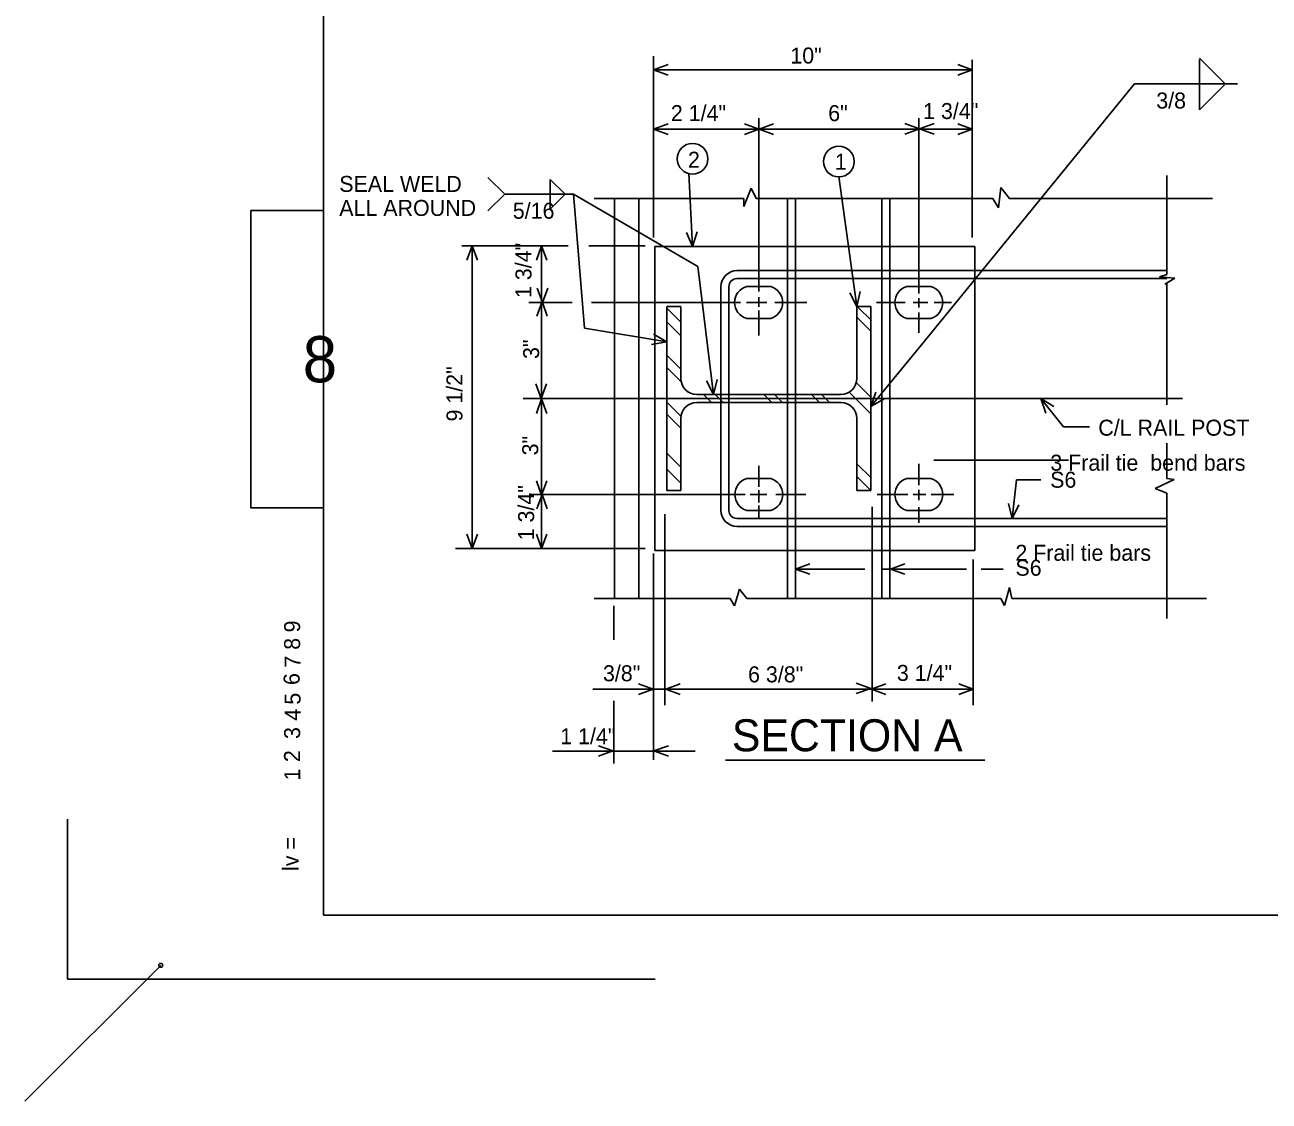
# Model space of a CAD drawing. Extents: x 1509.2 to 1521.3, y 1506 to 1514.6.
# Drawn here: x 1509.476 to 1512.715, y 1506.447 to 1509.25 of the extents above; entities that cross this region are included whole.
import ezdxf

# ---------------------------------------------------------------- set-up
doc = ezdxf.new("R2010")
doc.units = 0
for name, color, linetype in [('Level 1', 7, 'Continuous'), ('Level 2', 7, 'Continuous'), ('Level 3', 7, 'Continuous'), ('Level 4', 7, 'Continuous'), ('Level 49', 7, 'Continuous'), ('Level 5', 7, 'Continuous'), ('Level 50', 7, 'Continuous'), ('Level 6', 7, 'Continuous'), ('Level 7', 7, 'Continuous'), ('Level 8', 7, 'Continuous'), ('Level 9', 7, 'Continuous')]:
    doc.layers.add(name, color=color, linetype=linetype)

msp = doc.modelspace()

# ---------------------------------------------------------------- linework, layer by layer
at = {"layer": 'Level 1'}
for p, q in [((1510.2539, 1506.9309), (1510.2539, 1513.9308)), ((1510.2538, 1507.3188), (1510.2538, 1507.3116)), ((1509.5873, 1507.1817), (1509.5873, 1506.7643)), ((1510.2539, 1506.9309), (1520.7124, 1506.9309)), ((1509.5873, 1506.7643), (1511.1166, 1506.7643))]:
    msp.add_line(p, q, dxfattribs=at)
msp.add_lwpolyline([(1510.2539, 1508.7659), (1510.0647, 1508.7659), (1510.0647, 1507.992), (1510.2539, 1507.992)], close=True, dxfattribs=at)
at = {"layer": 'Level 2'}
for p, q in [((1511.113, 1508.696), (1511.113, 1509.1683)), ((1511.113, 1509.1323), (1511.1506, 1509.1459)), ((1511.113, 1509.1323), (1511.1506, 1509.1459)), ((1511.9419, 1509.1323), (1511.9043, 1509.1459)), ((1511.942, 1508.696), (1511.942, 1509.1588)), ((1512.5335, 1509.1626), (1512.5987, 1509.0973)), ((1512.5335, 1509.159), (1512.5335, 1509.0286)), ((1511.113, 1509.1323), (1511.9419, 1509.1323)), ((1511.113, 1509.1323), (1511.1506, 1509.1186)), ((1511.113, 1509.1323), (1511.1506, 1509.1186)), ((1511.9419, 1509.1323), (1511.9043, 1509.1186)), ((1511.8019, 1508.4068), (1512.3644, 1509.0956)), ((1512.3644, 1509.0956), (1512.6323, 1509.0956)), ((1512.5335, 1509.0286), (1512.5987, 1509.0938)), ((1511.3865, 1508.5549), (1511.3865, 1509.0069)), ((1511.8033, 1508.5501), (1511.8033, 1509.0069)), ((1511.113, 1508.978), (1511.1506, 1508.9917)), ((1511.113, 1508.978), (1511.1506, 1508.9917)), ((1511.113, 1508.978), (1511.9421, 1508.978)), ((1511.113, 1508.978), (1511.1506, 1508.9643)), ((1511.113, 1508.978), (1511.1506, 1508.9643)), ((1511.3867, 1508.9779), (1511.3491, 1508.9916)), ((1511.3867, 1508.9779), (1511.3491, 1508.9643)), ((1511.3873, 1508.978), (1511.4248, 1508.9917)), ((1511.3873, 1508.978), (1511.4248, 1508.9643)), ((1511.8046, 1508.979), (1511.767, 1508.9927)), ((1511.8046, 1508.979), (1511.767, 1508.9653)), ((1511.8052, 1508.979), (1511.8428, 1508.9927)), ((1511.8052, 1508.979), (1511.8428, 1508.9653)), ((1511.9421, 1508.978), (1511.9045, 1508.9917)), ((1511.9421, 1508.978), (1511.9045, 1508.9643)), ((1510.6818, 1508.8523), (1510.7255, 1508.8086)), ((1510.8824, 1508.8086), (1510.8437, 1508.8473)), ((1510.8437, 1508.7699), (1510.8437, 1508.8473)), ((1511.2142, 1508.6725), (1511.2046, 1508.8623)), ((1511.6418, 1508.5164), (1511.595, 1508.8551)), ((1512.449, 1508.5999), (1512.449, 1508.8569)), ((1511.3473, 1508.7764), (1511.3667, 1508.8246)), ((1511.3667, 1508.8246), (1511.3795, 1508.7975)), ((1512.0103, 1508.7733), (1512.0167, 1508.8262)), ((1512.0167, 1508.8262), (1512.0392, 1508.7975)), ((1510.6818, 1508.7649), (1510.7255, 1508.8086)), ((1510.9044, 1508.8086), (1510.7255, 1508.8086)), ((1510.8824, 1508.8086), (1510.8437, 1508.7699)), ((1511.2284, 1508.6201), (1510.9044, 1508.8086)), ((1510.9326, 1508.4598), (1510.9044, 1508.8086)), ((1510.9578, 1508.7975), (1511.3473, 1508.7975)), ((1511.0115, 1507.7559), (1511.0115, 1508.7975)), ((1511.074, 1507.7559), (1511.074, 1508.7975)), ((1511.3473, 1508.7975), (1511.3473, 1508.7764)), ((1511.3795, 1508.7975), (1511.9958, 1508.7975)), ((1511.4613, 1507.7559), (1511.4613, 1508.7974)), ((1511.4822, 1507.7559), (1511.4822, 1508.7974)), ((1511.707, 1507.7559), (1511.707, 1508.7974)), ((1511.7278, 1507.7559), (1511.7278, 1508.7974)), ((1511.9958, 1508.7975), (1512.0103, 1508.7733)), ((1512.0392, 1508.7975), (1512.5674, 1508.7975)), ((1511.2142, 1508.6725), (1511.1986, 1508.7093)), ((1511.2142, 1508.6725), (1511.2259, 1508.7108)), ((1510.8905, 1508.6743), (1510.6141, 1508.6743)), ((1510.6406, 1508.6743), (1510.6269, 1508.6367)), ((1510.6406, 1507.8863), (1510.6406, 1508.6743)), ((1510.6406, 1508.6743), (1510.6543, 1508.6367)), ((1510.8213, 1508.6743), (1510.8077, 1508.6367)), ((1510.8213, 1507.8863), (1510.8213, 1508.6743)), ((1510.8213, 1508.6743), (1510.835, 1508.6367)), ((1511.0913, 1508.6743), (1510.9442, 1508.6743)), ((1511.1157, 1508.6725), (1511.949, 1508.6725)), ((1511.1157, 1507.8808), (1511.1157, 1508.6725)), ((1511.949, 1507.8808), (1511.949, 1508.6725)), ((1511.269, 1508.2872), (1511.2284, 1508.6201)), ((1511.2284, 1508.6201), (1511.2284, 1508.6201)), ((1511.3298, 1508.6095), (1512.449, 1508.6095)), ((1511.3298, 1508.5887), (1512.449, 1508.5887)), ((1512.449, 1508.5999), (1512.4292, 1508.5935)), ((1512.4292, 1508.5935), (1512.4693, 1508.5903)), ((1512.4693, 1508.5903), (1512.4436, 1508.5743)), ((1510.8238, 1508.5268), (1510.8101, 1508.5643)), ((1510.8238, 1508.5268), (1510.8374, 1508.5643)), ((1511.2882, 1507.9853), (1511.2882, 1508.5678)), ((1511.3089, 1507.9852), (1511.3089, 1508.5678)), ((1511.3554, 1508.5685), (1511.4178, 1508.5685)), ((1511.6418, 1508.5164), (1511.6503, 1508.5555)), ((1511.7722, 1508.5685), (1511.8345, 1508.5685)), ((1512.449, 1508.2602), (1512.449, 1508.579)), ((1510.7882, 1508.5268), (1510.9013, 1508.5268)), ((1510.8225, 1508.5288), (1510.8088, 1508.4913)), ((1510.8225, 1508.5288), (1510.8362, 1508.4913)), ((1510.9513, 1508.5268), (1511.3394, 1508.5268)), ((1511.3547, 1508.5268), (1511.4075, 1508.5268)), ((1511.3865, 1508.515), (1511.3865, 1508.5408)), ((1511.4286, 1508.5268), (1511.5118, 1508.5268)), ((1511.6418, 1508.5164), (1511.6232, 1508.5518)), ((1511.6931, 1508.5268), (1511.7672, 1508.5268)), ((1511.7883, 1508.5268), (1511.8262, 1508.5268)), ((1511.8033, 1508.5138), (1511.8033, 1508.5379)), ((1511.8428, 1508.5268), (1511.8881, 1508.5268)), ((1511.147, 1508.0372), (1511.147, 1508.5164)), ((1511.147, 1508.5164), (1511.1835, 1508.5164)), ((1511.1835, 1508.4758), (1511.148, 1508.5113)), ((1511.1835, 1508.3288), (1511.1835, 1508.5164)), ((1511.3865, 1508.4411), (1511.3865, 1508.5057)), ((1511.677, 1508.4525), (1511.6415, 1508.488)), ((1511.6418, 1508.5164), (1511.6783, 1508.5164)), ((1511.6418, 1508.3288), (1511.6418, 1508.5164)), ((1511.6797, 1508.4793), (1511.6442, 1508.5148)), ((1511.6783, 1508.0372), (1511.6783, 1508.5164)), ((1511.8033, 1508.4473), (1511.8033, 1508.5002)), ((1511.147, 1508.4246), (1510.9326, 1508.4598)), ((1511.1829, 1508.4406), (1511.1474, 1508.4761)), ((1511.3554, 1508.4851), (1511.4178, 1508.4851)), ((1511.7722, 1508.4851), (1511.8345, 1508.4851)), ((1511.147, 1508.4246), (1511.1077, 1508.4172)), ((1511.147, 1508.4246), (1511.1122, 1508.4442)), ((1511.6783, 1508.2555), (1511.8054, 1508.4111)), ((1511.1848, 1508.3524), (1511.1493, 1508.3879)), ((1511.1848, 1508.3203), (1511.1493, 1508.3558)), ((1511.269, 1508.2872), (1511.278, 1508.3262)), ((1510.8202, 1508.2769), (1510.8065, 1508.3145)), ((1510.8202, 1508.2769), (1510.8338, 1508.3145)), ((1511.269, 1508.2872), (1511.2508, 1508.3228)), ((1511.6783, 1508.2798), (1511.6397, 1508.3184)), ((1510.7732, 1508.2768), (1512.4893, 1508.2768)), ((1510.8213, 1508.2755), (1510.8077, 1508.2379)), ((1510.8213, 1508.2755), (1510.835, 1508.2379)), ((1511.1835, 1508.2309), (1511.148, 1508.2664)), ((1511.2252, 1508.2872), (1511.6002, 1508.2872)), ((1511.2252, 1508.2664), (1511.6002, 1508.2664)), ((1511.2638, 1508.2664), (1511.2421, 1508.2881)), ((1511.2936, 1508.2664), (1511.2719, 1508.2881)), ((1511.4204, 1508.2664), (1511.3988, 1508.2881)), ((1511.4478, 1508.2671), (1511.4262, 1508.2888)), ((1511.5443, 1508.2664), (1511.5227, 1508.2881)), ((1511.5711, 1508.2664), (1511.5494, 1508.2881)), ((1511.6783, 1508.2368), (1511.6218, 1508.2934)), ((1511.6783, 1508.2555), (1511.6915, 1508.2933)), ((1511.6783, 1508.2555), (1511.7127, 1508.2759)), ((1512.1801, 1508.2026), (1512.1207, 1508.2768)), ((1512.1207, 1508.2768), (1512.1335, 1508.2388)), ((1512.1207, 1508.2768), (1512.1548, 1508.256)), ((1511.1829, 1508.2006), (1511.1474, 1508.2361)), ((1511.1835, 1508.0372), (1511.1835, 1508.2248)), ((1511.6418, 1508.0372), (1511.6418, 1508.2248)), ((1512.1801, 1508.2026), (1512.2476, 1508.2026)), ((1511.1835, 1508.0975), (1511.148, 1508.133)), ((1512.449, 1508.0687), (1512.449, 1508.1604)), ((1511.3865, 1508.047), (1511.3865, 1508.101)), ((1511.6797, 1508.0689), (1511.6409, 1508.1076)), ((1511.8033, 1508.0511), (1511.8033, 1508.1061)), ((1511.8422, 1508.1158), (1512.193, 1508.1158)), ((1511.1835, 1508.0564), (1511.148, 1508.0919)), ((1511.3554, 1508.0684), (1511.4178, 1508.0684)), ((1511.6785, 1508.0368), (1511.643, 1508.0723)), ((1511.7722, 1508.0684), (1511.8345, 1508.0684)), ((1512.449, 1508.0687), (1512.4677, 1508.0654)), ((1510.8213, 1508.0247), (1510.8077, 1508.0623)), ((1510.8213, 1508.0247), (1510.835, 1508.0623)), ((1511.147, 1508.0372), (1511.1835, 1508.0372)), ((1511.3865, 1508.0059), (1511.3865, 1508.0376)), ((1511.6418, 1508.0372), (1511.6783, 1508.0372)), ((1511.8033, 1508.0118), (1511.8033, 1508.039)), ((1512.0459, 1507.9643), (1512.0574, 1508.0646)), ((1512.0574, 1508.0646), (1512.1206, 1508.0646)), ((1512.4677, 1508.0654), (1512.4185, 1508.0421)), ((1512.4185, 1508.0421), (1512.449, 1508.0301)), ((1510.7905, 1508.0267), (1511.3512, 1508.0267)), ((1510.8225, 1508.0268), (1510.8088, 1507.9893)), ((1510.8225, 1508.0268), (1510.8362, 1507.9893)), ((1511.3641, 1508.0267), (1511.4075, 1508.0267)), ((1511.4309, 1508.0267), (1511.5095, 1508.0267)), ((1511.6948, 1508.0267), (1511.7748, 1508.0267)), ((1511.7883, 1508.0267), (1511.8216, 1508.0267)), ((1511.8352, 1508.0267), (1511.8942, 1508.0267)), ((1512.0459, 1507.9643), (1512.0366, 1508.0033)), ((1512.449, 1507.7035), (1512.449, 1508.0301)), ((1511.1419, 1507.9754), (1511.1419, 1507.4778)), ((1511.3554, 1507.985), (1511.4178, 1507.985)), ((1511.3865, 1507.9661), (1511.3865, 1507.9978)), ((1511.6818, 1507.9947), (1511.6818, 1507.4874)), ((1511.7722, 1507.985), (1511.8345, 1507.985)), ((1511.8033, 1507.9528), (1511.8033, 1507.9937)), ((1512.0459, 1507.9643), (1512.0638, 1508.0001)), ((1511.3298, 1507.9643), (1512.449, 1507.9643)), ((1511.3298, 1507.9436), (1512.449, 1507.9436)), ((1510.6406, 1507.8863), (1510.6269, 1507.9238)), ((1510.6406, 1507.8863), (1510.6543, 1507.9238)), ((1510.8213, 1507.8863), (1510.8077, 1507.9238)), ((1510.8213, 1507.8863), (1510.835, 1507.9238)), ((1511.0913, 1507.8863), (1510.5973, 1507.8863)), ((1511.1126, 1507.8728), (1511.1126, 1507.3361)), ((1511.1157, 1507.8808), (1511.949, 1507.8808)), ((1511.4822, 1507.8326), (1511.5198, 1507.8463)), ((1511.7295, 1507.8326), (1511.7671, 1507.8463)), ((1511.9444, 1507.8573), (1511.9444, 1507.4778)), ((1511.4822, 1507.8326), (1511.6624, 1507.8326)), ((1511.4822, 1507.8326), (1511.5198, 1507.8189)), ((1511.7065, 1507.8326), (1511.927, 1507.8326)), ((1511.7295, 1507.8326), (1511.7671, 1507.8189)), ((1511.9653, 1507.8326), (1512.0228, 1507.8326)), ((1511.3233, 1507.7364), (1511.3362, 1507.7798)), ((1511.3362, 1507.7798), (1511.3554, 1507.7559)), ((1512.0263, 1507.738), (1512.0392, 1507.7846)), ((1512.0392, 1507.7846), (1512.0456, 1507.7559)), ((1510.9578, 1507.7559), (1511.3121, 1507.7559)), ((1511.3121, 1507.7559), (1511.3233, 1507.7364)), ((1511.3554, 1507.7559), (1512.0167, 1507.7559)), ((1512.0167, 1507.7559), (1512.0263, 1507.738)), ((1512.0456, 1507.7559), (1512.5523, 1507.7559)), ((1511.0093, 1507.7367), (1511.0093, 1507.6485)), ((1510.9548, 1507.5199), (1511.9446, 1507.5199)), ((1511.1114, 1507.5199), (1511.0738, 1507.5336)), ((1511.1114, 1507.5199), (1511.0738, 1507.5063)), ((1511.1447, 1507.5199), (1511.1823, 1507.5336)), ((1511.1447, 1507.5199), (1511.1823, 1507.5063)), ((1511.6781, 1507.5218), (1511.6405, 1507.5355)), ((1511.6781, 1507.5218), (1511.6405, 1507.5082)), ((1511.6797, 1507.5199), (1511.7173, 1507.5336)), ((1511.6797, 1507.5199), (1511.7173, 1507.5063)), ((1511.9446, 1507.5199), (1511.907, 1507.5336)), ((1511.9446, 1507.5199), (1511.907, 1507.5063)), ((1511.0093, 1507.4893), (1511.0093, 1507.3263)), ((1510.8493, 1507.3584), (1511.2214, 1507.3584)), ((1511.0069, 1507.3588), (1510.9693, 1507.3725)), ((1511.0069, 1507.3588), (1510.9693, 1507.3452)), ((1511.1138, 1507.3588), (1511.1514, 1507.3725)), ((1511.1138, 1507.3588), (1511.1514, 1507.3452)), ((1511.3003, 1507.3353), (1511.9748, 1507.3353)), ((1509.4764, 1506.4471), (1509.83, 1506.8006))]:
    msp.add_line(p, q, dxfattribs=at)
for centre in [(1511.2142, 1508.9008), (1511.595, 1508.8936)]:
    msp.add_circle(centre, 0.04, dxfattribs=at)
for centre, radius, start, end in [((1511.3299, 1508.5678), 0.0417, 90, 180), ((1511.3297, 1508.5679), 0.0208, 90, 180), ((1511.3667, 1508.5268), 0.0432, 105.151, 254.849), ((1511.4048, 1508.5268), 0.0437, 287.2, 72.8), ((1511.784, 1508.5268), 0.0434, 105.8765, 254.1235), ((1511.8216, 1508.5268), 0.0437, 287.2, 72.8), ((1511.2252, 1508.3289), 0.0417, 180, 270), ((1511.6001, 1508.3289), 0.0417, 270, 0), ((1511.2252, 1508.2247), 0.0417, 90, 180), ((1511.6001, 1508.2247), 0.0417, 0, 90), ((1511.3677, 1508.0267), 0.0435, 106.4619, 253.5381), ((1511.4052, 1508.0267), 0.0436, 286.7563, 73.2437), ((1511.784, 1508.0267), 0.0434, 105.8765, 254.1235), ((1511.8221, 1508.0267), 0.0435, 286.609, 73.391), ((1511.3299, 1507.9853), 0.0417, 180, 270), ((1511.3297, 1507.9851), 0.0208, 180, 270)]:
    msp.add_arc(centre, radius, start, end, dxfattribs=at)
at = {"layer": 'Level 49'}
msp.add_circle((1509.83, 1506.8006), 0.00506, dxfattribs=at)

# ---------------------------------------------------------------- texts
at = {"layer": 'Level 1'}
msp.add_text('8', height=0.1204, dxfattribs=at).set_placement((1510.1996, 1508.3187))
msp.add_text('1', height=0.0417, rotation=90, dxfattribs=at).set_placement((1510.1931, 1507.282))
at = {"layer": 'Level 2'}
for s, height, rotation, p in [('10"', 0.04167, 0, (1511.4688, 1509.1488)), ('3/8', 0.04167, 0, (1512.4212, 1509.0317)), ('1 3/4"', 0.04167, 0, (1511.8143, 1509.0043)), ('2', 0.0417, 0, (1511.2023, 1508.8775)), ('1', 0.0417, 0, (1511.5845, 1508.8723)), ('SEAL WELD', 0.04167, 0, (1510.2947, 1508.8145)), ('ALL AROUND', 0.04167, 0, (1510.2947, 1508.752)), ('5/16', 0.04167, 0, (1510.7464, 1508.7447)), ('1 3/4"', 0.04167, 90, (1510.7949, 1508.5383)), ('3"', 0.04167, 90, (1510.8148, 1508.3795)), ('9 1/2"', 0.04167, 90, (1510.6154, 1508.2168)), ('C/L RAIL POST', 0.041667, 0, (1512.2703, 1508.1798)), ('3"', 0.04167, 90, (1510.8125, 1508.1285)), ('1 3/4"', 0.04167, 90, (1510.8019, 1507.9073)), ('3/8"', 0.04167, 0, (1510.9811, 1507.5403)), ('6 3/8"', 0.04167, 0, (1511.3587, 1507.5375)), ('3 1/4"', 0.04167, 0, (1511.7461, 1507.5413)), ('1 1/4"', 0.04167, 0, (1510.8698, 1507.3764)), ('SECTION A', 0.08333, 0, (1511.3165, 1507.358)), ('2', 0.0417, 90, (1510.1926, 1507.3299)), ('lv =', 0.04167, 90, (1510.1887, 1507.0464))]:
    msp.add_text(s, height=height, rotation=rotation, dxfattribs=at).set_placement(p)
for s, p in [('2 1/4"', (1511.1578, 1508.9988)), ('6"', (1511.5673, 1508.9988)), ('S6  ', (1512.145, 1508.0443)), ('S6  ', (1512.0546, 1507.8151))]:
    msp.add_text(s, height=0.04167, dxfattribs=at).set_placement(p)
at = {"layer": 'Level 3'}
msp.add_text('3', height=0.0417, rotation=90, dxfattribs=at).set_placement((1510.1928, 1507.39))
at = {"layer": 'Level 4'}
msp.add_text('4', height=0.0417, rotation=90, dxfattribs=at).set_placement((1510.194, 1507.4377))
at = {"layer": 'Level 5'}
msp.add_text('5', height=0.0417, rotation=90, dxfattribs=at).set_placement((1510.194, 1507.4793))
at = {"layer": 'Level 50'}
for s, p in [('3 Frail tie  bend bars', (1512.1454, 1508.0886)), ('2 Frail tie bars', (1512.0545, 1507.854))]:
    msp.add_text(s, height=0.041667, dxfattribs=at).set_placement(p)
at = {"layer": 'Level 6'}
msp.add_text('6', height=0.0417, rotation=90, dxfattribs=at).set_placement((1510.1916, 1507.5306))
at = {"layer": 'Level 7'}
msp.add_text('7', height=0.0417, rotation=90, dxfattribs=at).set_placement((1510.194, 1507.5758))
at = {"layer": 'Level 8'}
msp.add_text('8', height=0.0417, rotation=90, dxfattribs=at).set_placement((1510.1928, 1507.6223))
at = {"layer": 'Level 9'}
msp.add_text('9', height=0.0417, rotation=90, dxfattribs=at).set_placement((1510.1928, 1507.6675))

doc.saveas('drawing.dxf')
